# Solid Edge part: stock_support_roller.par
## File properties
Density: 0 kg/mm^3
Accuracy: 0.99
Title: Stock support roller
Author: Abhinav Rai
Template: Normal.par
Last saved by: TIET
Revision: 15
Application: Solid Edge
Material: aluminum
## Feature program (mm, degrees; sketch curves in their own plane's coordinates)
sketch for "unnamed RevolvedProtrusion 1" plane through (0, 0, 0) normal (0, -1, 0) x-axis (1, 0, 0)
  line (60, 0) -> (60, 24.638)
  line (60, 24.638) -> (15.55, 24.638)
  line (15.55, 24.638) -> (15.55, 92.075)
  line (15.55, 92.075) -> (-2.2388, 92.075)
  line (-2.2388, 92.075) -> (-111.45, 29.0219)
  line (-220.6612, 92.075) -> (-111.45, 29.0219)
  line (-238.45, 92.075) -> (-220.6612, 92.075)
  line (-238.45, 24.638) -> (-238.45, 92.075)
  line (-282.9, 24.638) -> (-238.45, 24.638)
  line (-282.9, 0) -> (-282.9, 24.638)
revolve "unnamed RevolvedProtrusion 1" add full turn 360 deg about sketch line (-282.9, 0) -> (60, 0)
chamfer "unnamed Chamfer 1"
fillet "Round_1" radius 1.5748
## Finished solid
Body 1: solid body, 14 faces, 13 edges, 0 vertices.
  Faces by surface: cone 4, cylinder 4, plane 4, torus 2
  Edges by curve: circle 13
Bounding box of the edges (mm; curved faces can reach further): 342.900 x 184.150 x 184.150, from (-282.9, -92.075, -92.075) to (60, 92.075, 92.075).
Cylindrical faces by radius (mm): R24.638 x2, R92.075 x2
Conical faces (half-angle, radius in mm at the cone's reference point): 30 deg R29.0219 x1, 30 deg R92.075 x1, 45 deg R23.0632 x1, 45 deg R24.638 x1
Toroidal faces (ring radius, tube radius in mm): R26.2128 r1.5748 x2
Planar faces by outward normal: +x 2, -x 2
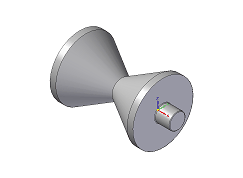
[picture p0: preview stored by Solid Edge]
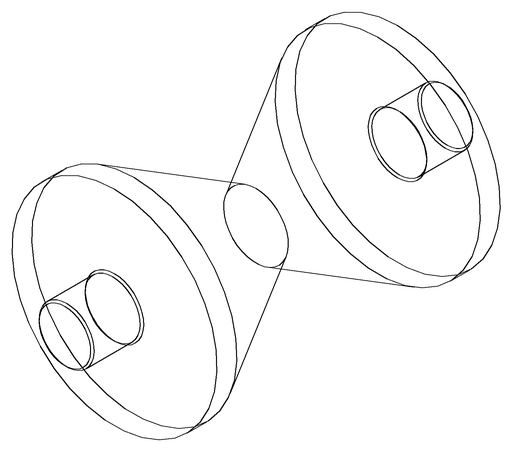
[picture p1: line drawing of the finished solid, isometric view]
